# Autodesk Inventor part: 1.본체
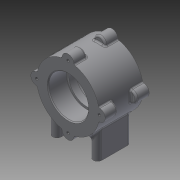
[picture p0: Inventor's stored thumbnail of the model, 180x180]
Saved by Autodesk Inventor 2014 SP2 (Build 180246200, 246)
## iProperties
Created: 2015-03
Part Number: 1.본체
Material: 일반
Document SubType Name: Modeling
Designer: 2015.02.10
Density: 1 g/cm^3
Appearance: 기본값
Author: 2015.02.10
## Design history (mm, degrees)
sketch "스케치1"
  geometry: C1 r 37 at (0, 0); 1 further point
  constraints: 1 centre point, 1 coincident
  dimensions: "d0" = 74 diameter of C1
extrude "돌출1" new body sketch "스케치1" distance "d1" = 52; taper "d2" = 0 deg
sketch "스케치2"
  geometry: A1 r 7 centre (-0.033, 37) between (6.936, 36.344) and (-7.001, 36.332); A2 r 37 centre (0, 0) between (-0.033, 37) and (-7.001, 36.332) reference; 2 further points
  constraints: 5 point on circle, 1 centre point, 2 other
  dimensions: "d3" = 14 diameter of A1; "d4" = 36.99999 distance of point (0, 0) A1.centre
extrude "돌출2" join sketch "스케치2" distance "d5" = 15; taper "d6" = 0 deg
node "작업 평면1"
sketch "스케치3"
  geometry: C1 r 23.5 at (0, 0); 1 further point
  constraints: 1 centre point, 1 coincident
  dimensions: "d10" = 47 diameter of C1
extrude "돌출3" cut sketch "스케치3" distance "d11" = 22; taper "d12" = 0 deg
sketch "스케치4"
  geometry: C1 r 21 at (0, 0); 1 further point
  constraints: 1 centre point, 1 coincident
  dimensions: "d13" = 42 diameter of C1
extrude "돌출4" cut sketch "스케치4" stored distance "d14" = 22; taper "d15" = 0 deg
sketch "스케치6" dims "d16" = 74
  geometry: C1 r 2 at (0, 37); A1 r 7 centre (-0.033, 37) between (6.936, 36.344) and (-7.001, 36.332) reference; 2 further points
  constraints: 1 centre point, 1 coincident, 1 vertical alignment, 2 other
  dimensions: "d17" = 4 diameter of C1; "d18" = 0.00001 vertical distance of C1.centre A1.centre
hole "구멍1" sketch "스케치6" at (0, 37) diameter "d19" = 3.242; stored, may be unused: countersink angle "d23" = 90 deg, drill point angle "d25" = 118 deg; dims "d20" = 8, "d21" = 4, "d22" = 2, "d24" = 11
sketch "스케치9"
  geometry: L1 (29, -22.978)-(29, -56); L2 (29, -56)-(19, -56); L3 (19, -56)-(19, -31.749); L4 (-29, -22.978)-(-29, -56); L5 (-29, -56)-(-19, -56); L6 (-19, -56)-(-19, -31.749); A1 r 37 centre (0, 0) between (7.001, -36.332) and (36.344, -6.936) reference; A2 r 37 centre (0, 0) between (-36.332, -7.001) and (-6.936, -36.344) reference; 1 further point
  constraints: 12 end point, 4 point on circle, 3 parallel, 2 perpendicular, 1 vertical
  dimensions: "d29" = 56 distance from line of L2 point (0, 0); "d30" = 10 distance of L4.end L5.end; "d31" = 10 distance of L1.end L2.end; "d34" = 48 distance between parallel lines of L1 L6; "d35" = 0 distance between parallel lines of L2 L5; "d36" = 7.344 distance from line of A1.end L1
extrude "돌출5" join sketch "스케치9" stored distance "d37" = 40; taper "d38" = 0 deg
sketch "스케치10"
  geometry: L1 (10, 40)-(10, 0) reference; L2 (0, 40)-(0, 0) reference; L3 (10, 20)-(7.36, 20); C1 r 2.5 at (5, 5); C2 r 2.5 at (5, 35); 1 further point
  constraints: 2 centre point, 2 end point, 1 midpoint, 1 perpendicular, 1 symmetric about line, 1 other
  dimensions: "d39" = 5 diameter of C1; "d40" = 15 distance from line of C1.centre L3; "d41" = 5 distance from line of L1 C1.centre
hole "구멍2" sketch "스케치10" at (5, 5), (5, 35) diameter "d42" = 4.459; stored, may be unused: countersink angle "d46" = 90 deg, drill point angle "d48" = 118 deg; dims "d43" = 6, "d44" = 4, "d45" = 2, "d47" = 8
fillet "모깎기1" dims "d51" = 2
fillet "모깎기2" dims "d50" = 5
fillet "모깎기3" dims "d55" = 5
fillet "모깎기4" dims "d56" = 0.3
chamfer "모따기1" distance "d57" = 1; stored, may be unused: second distance "d58" = 2, angle "d59" = 45 deg
chamfer "모따기2" distance "d60" = 1; stored, may be unused: second distance "d61" = 2, angle "d62" = 45 deg
node "작업 평면3"
sketch "스케치11"
  geometry: L1 (-52, 19.462)-(-52, -19.462) reference; L2 (-52, 0)-(-26, 0); L3 (-46.602, 3.031)-(-5.123, 3.031); L4 (-5.123, 3.031)-(-5.123, -2.974); L5 (-5.123, -2.974)-(-46.602, -2.974); L6 (-46.602, -2.974)-(-46.602, 3.031); 2 further points
  constraints: 2 end point, 1 coincident, 1 midpoint, 1 perpendicular, 2 other
  dimensions: "d63" = 26 distance of L2.start L2.end
feature "엠보싱1" sketch "스케치11" dims "d1" = 52, "d64" = 0.5, "d65" = 0
node "솔리드1"
pattern_circular "원형 패턴1" dims angle "d8" = 360 deg
mirror "대칭1"
mirror "대칭2"
pattern_circular "원형 패턴2" dims angle "d27" = 360 deg
mirror "대칭3"
mirror "대칭4"
pattern_circular "원형 패턴3" dims angle "d53" = 360 deg
mirror "대칭5"
mirror "대칭6"
mirror "대칭7"
node "투영된 루프1"
